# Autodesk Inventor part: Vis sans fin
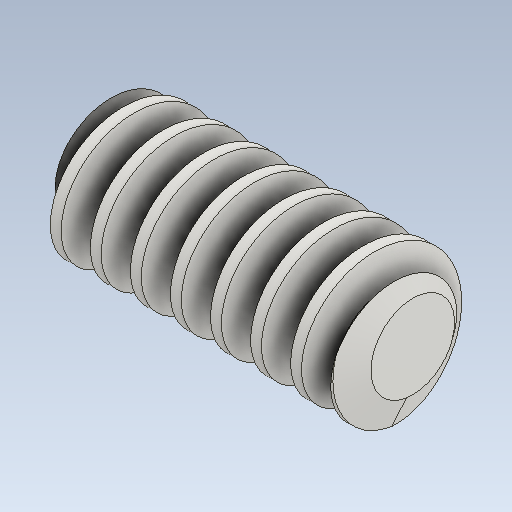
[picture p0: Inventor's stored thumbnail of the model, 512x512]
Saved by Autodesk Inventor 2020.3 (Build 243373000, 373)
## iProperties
CustomPartVersion: 1
Created: 2020-11
Part Number: Vis sans fin
Material: Steel, Mild
Document SubType Name: Modeling
Designer: ficho
Categories: <?xml version="1.0" encoding="UTF-16"?> <MemberInstance><Categories><FamilyTemplate><FamilyTemplateParameter ValueType="xs:double" Id="1" ObjectReferenceKey="da
Density: 7.85 g/cm^3
Appearance: Steel
Mass: 3.35407 g
Surface Area: 6.05359 cm^2
Volume: 0.42727 cm^3
Author: ficho
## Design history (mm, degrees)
body "Solid1"
extrude "Corps de base" new body stored distance "d6" = 16 (= da_b); taper "d7" = 0 deg
chamfer "Chamfer1" distance "d8" = 0.51792 (= fd_cham1); stored, may be unused: second distance "d9" = 1.42297 (= 0.5 x fd_cham2), angle "d47" = 45 deg
chamfer "Chamfer2" distance "d10" = 0.51792 (= fd_cham1); stored, may be unused: second distance "d11" = 1.42297 (= 0.5 x fd_cham2), angle "d48" = 45 deg
sketch "Esquisse de la dent"
  geometry: L1 (0, 3.557)-(0, 1.52) reference; L2 (-9.961, 3.593)-(-9.43, 2.134); L3 (-8.972, 2.134)-(-8.441, 3.593); L4 (-10.279, 0)-(-8.153, 0) reference; L5 (-9.961, 3.593)-(-9.201, 3.593); L6 (-9.201, 3.593)-(-8.441, 3.593); L7 (-9.43, 2.134)-(-9.201, 2.134); L8 (-9.201, 2.134)-(-8.972, 2.134); L9 (-9.201, 2.911)-(-8.69, 2.911); L10 (-9.201, 3.593)-(-9.201, 2.134)
  constraints: 16 end point, 3 equal length, 3 parallel, 2 collinear, 2 point on line
  dimensions: "d24" = 110 deg angle of L7 L2 (computed from da_alfat); "d25" = 9.20097 distance from line of L1 L5.end (= fd_dist); "d26" = 0.51117 distance of L9.start L9.end (= 0.25 x da_px); "d27" = 2.13446 distance between parallel lines of L4 L7 (= 0.5 x da_df); "d28" = 2.91063 distance between parallel lines of L4 L9 (= 0.5 x da_d); "d29" = 3.59301 distance between parallel lines of L4 L5 (= 0.505 x da_da)
feature "Dent" pitch "d30" = 2.04466 (computed from da_px, da_z); turns "d32" = 10 (= fd_n); dims "d31" = 10, "d33" = 0, angle "d34" = 90 deg, angle "d35" = 90 deg, "d36" = 0, "d37" = 0, "d70" = 10, "da_rightdir" = 0 [user parameter]
pattern_circular "Motif de la dent" dims angle "d46" = 360 deg, "da_rightdir" = 0 [user parameter]
feature "Dent gauche" pitch "d62" = 2.04466 (computed from da_px, da_z); turns "d64" = 10 (= fd_n); dims "d63" = 10, "d65" = 0, angle "d66" = 90 deg, angle "d67" = 90 deg, "d68" = 0, "d69" = 0, "d76" = 10, "da_rightdir" = 0 [user parameter]
pattern_circular "Motif de dent gauche" dims angle "d73" = 360 deg, "da_rightdir" = 0 [user parameter]
node "Esquisse du corps de base" dims "d5" = 7.11486 (= da_da)
sketch "Sketch5"
  geometry: C1 r 3.557 at (0, 0) reference; C2 r 2.911 at (0, 0)
  constraints: 1 centre point, 1 coincident
  dimensions: "d59" = 5.82125 diameter of C2 (= da_d)
body "Srf1"
feature "Diamètre primitif" dims "d60" = 10, "d61" = 0
other parameters: "da_aw" = 12.5 [user parameter; used in 2 equation terms], "da_b" = 16 [user parameter; used in 3 equation terms], "da_df" = 4.26892 [user parameter; used in 2 equation terms], "da_da" = 7.11486 [user parameter; used in 3 equation terms], "fd_cham2" = 2.84595 (= da_da - da_df) [user parameter; used in 3 equation terms], "fd_cham1" = 0.51792 (= 0.181985 x fd_cham2) [user parameter; used in 2 equation terms], "da_d" = 5.82125 [user parameter; used in 2 equation terms], "da_px" = 2.04466 [user parameter; used in 5 equation terms], "fd_dist" = 9.20097 (computed from da_b, da_px) [user parameter; used in 1 equation term], "fd_n" = 10 (computed from da_b, da_px) [user parameter; used in 2 equation terms], "da_alfat" = 20 deg [user parameter; used in 1 equation term], "d12" = 110 deg (derived), "d14" = 3.1425 (derived), "d49" = 12.5 (= da_aw), "d50" = 0, "d54" = 0, "d56" = 0, "d77" = 0, "d79" = 12.5 (= da_aw), "d80" = 0
